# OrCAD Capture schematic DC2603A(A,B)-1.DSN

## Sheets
1 PAGE2: size Custom; title: DC/DC    MODULE REGULATOR; rev: 1; company: TM
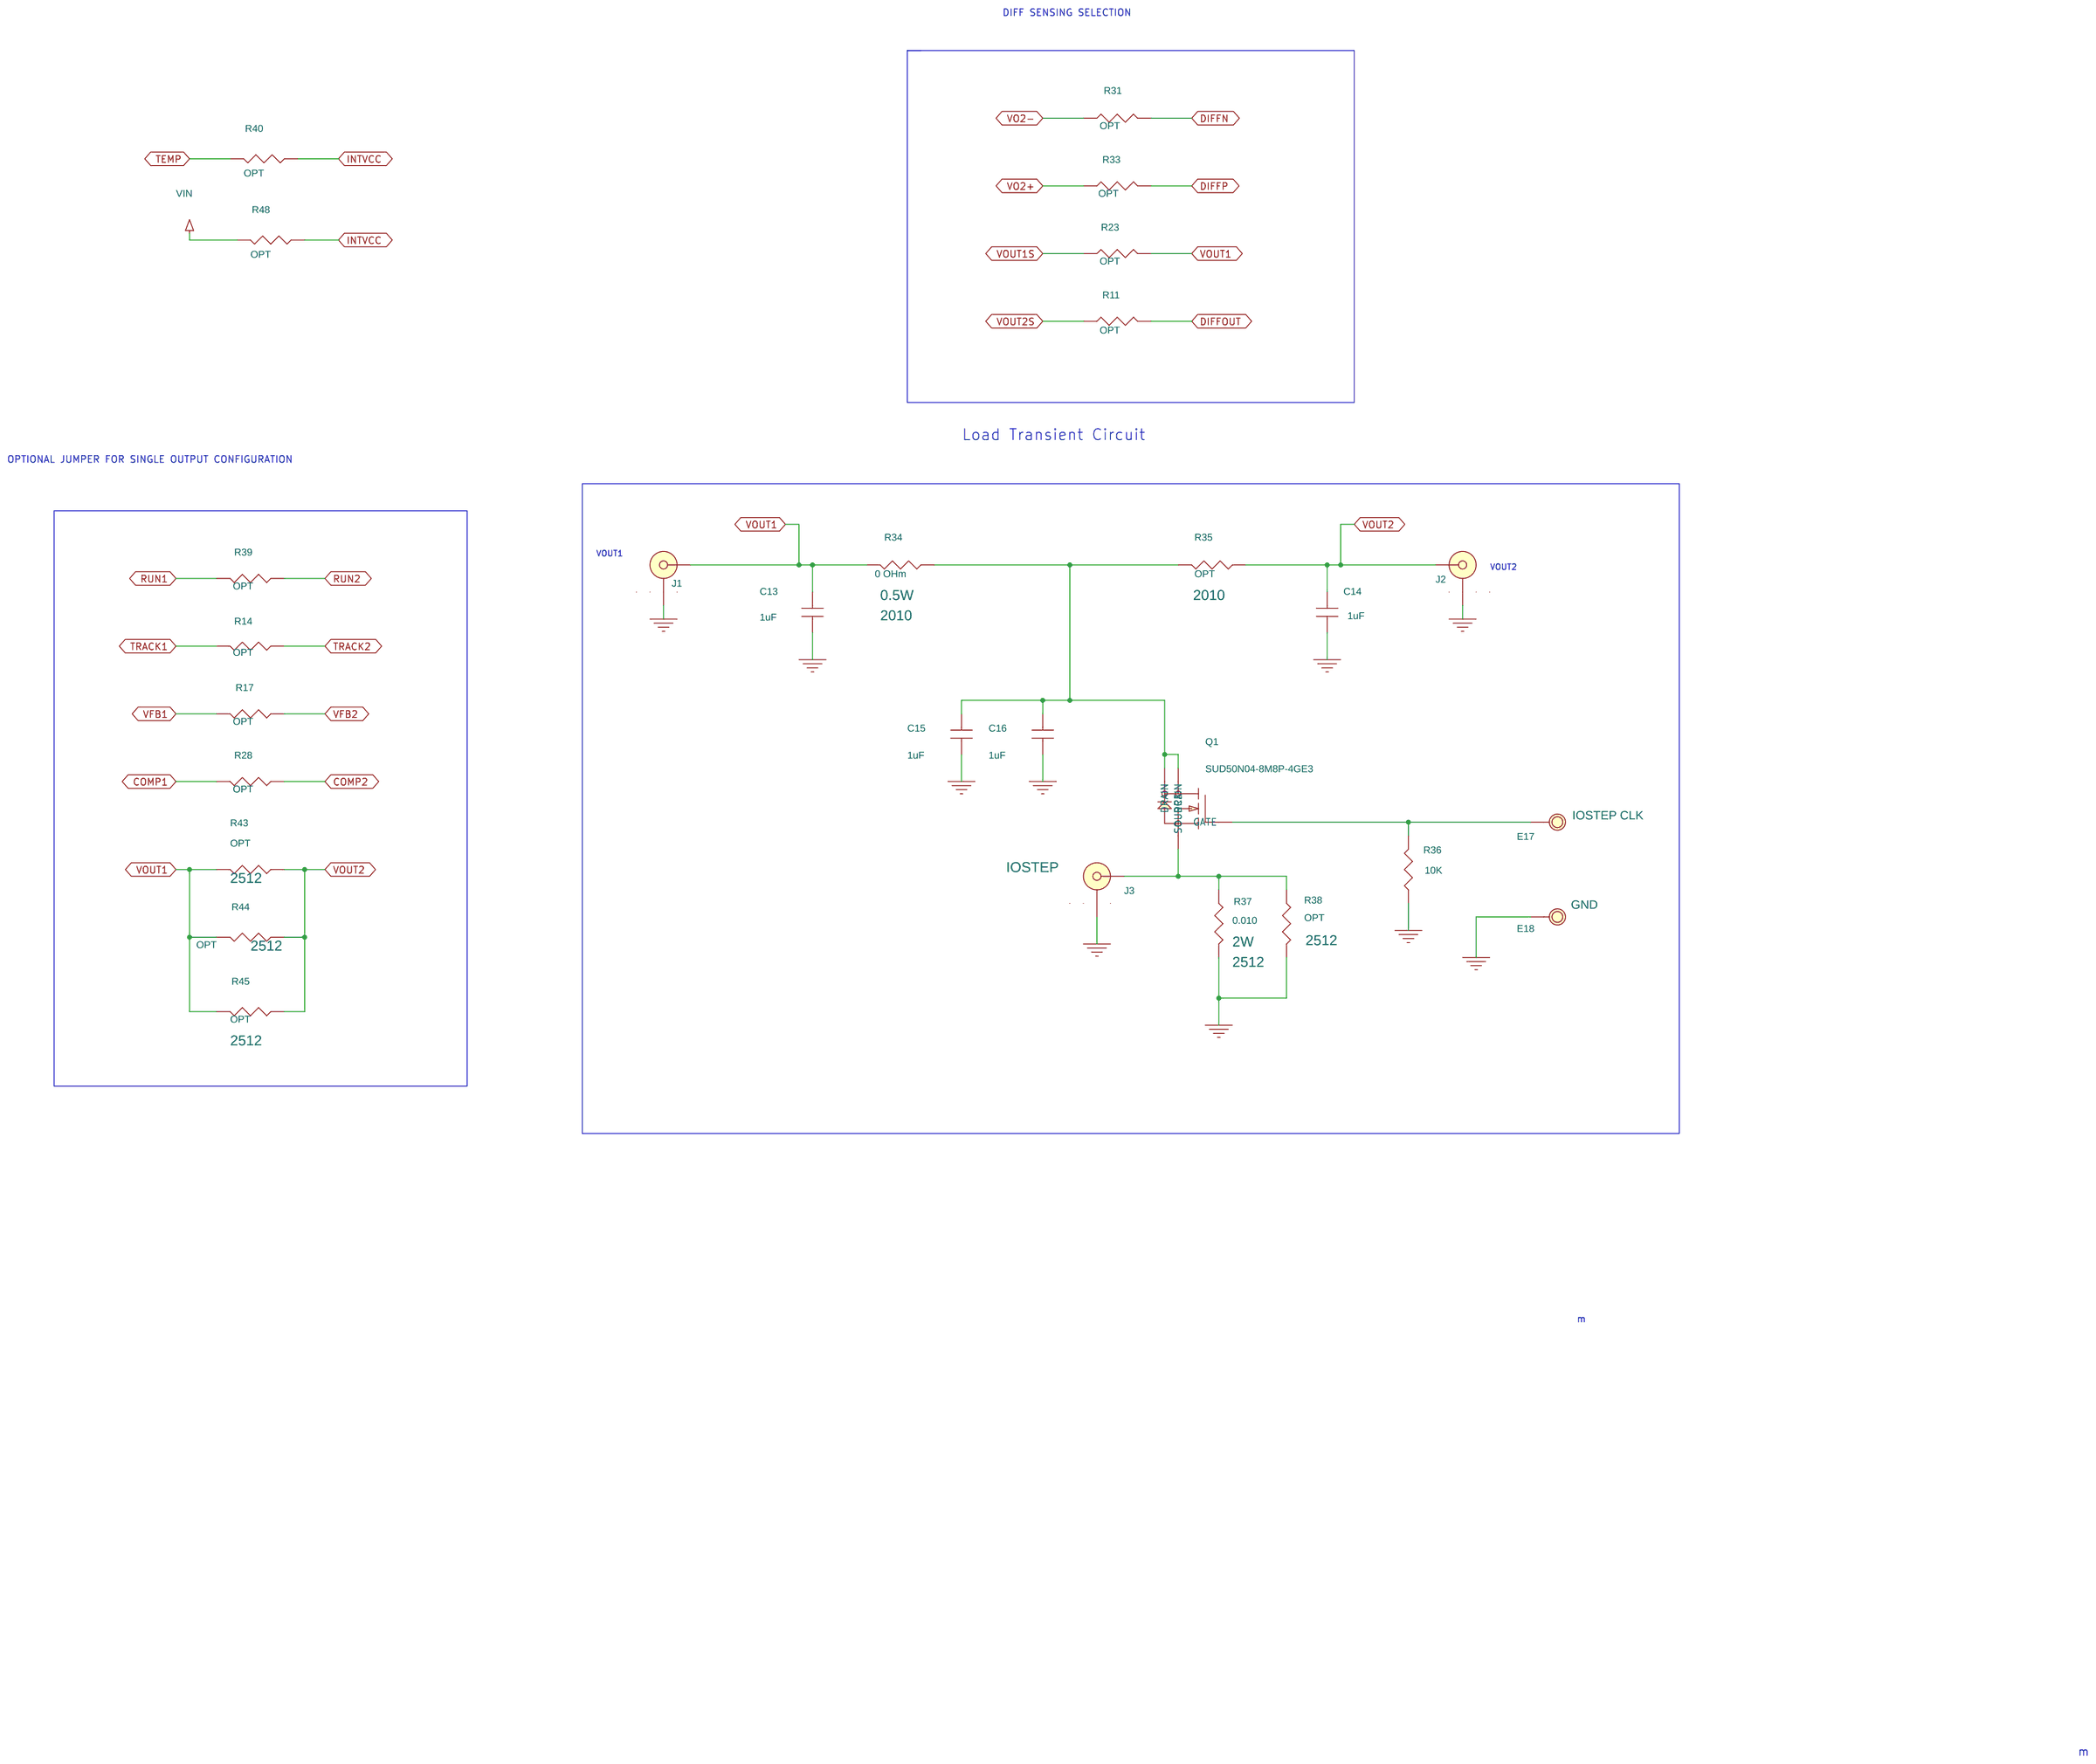
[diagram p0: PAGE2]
2 LTM4650: size Custom
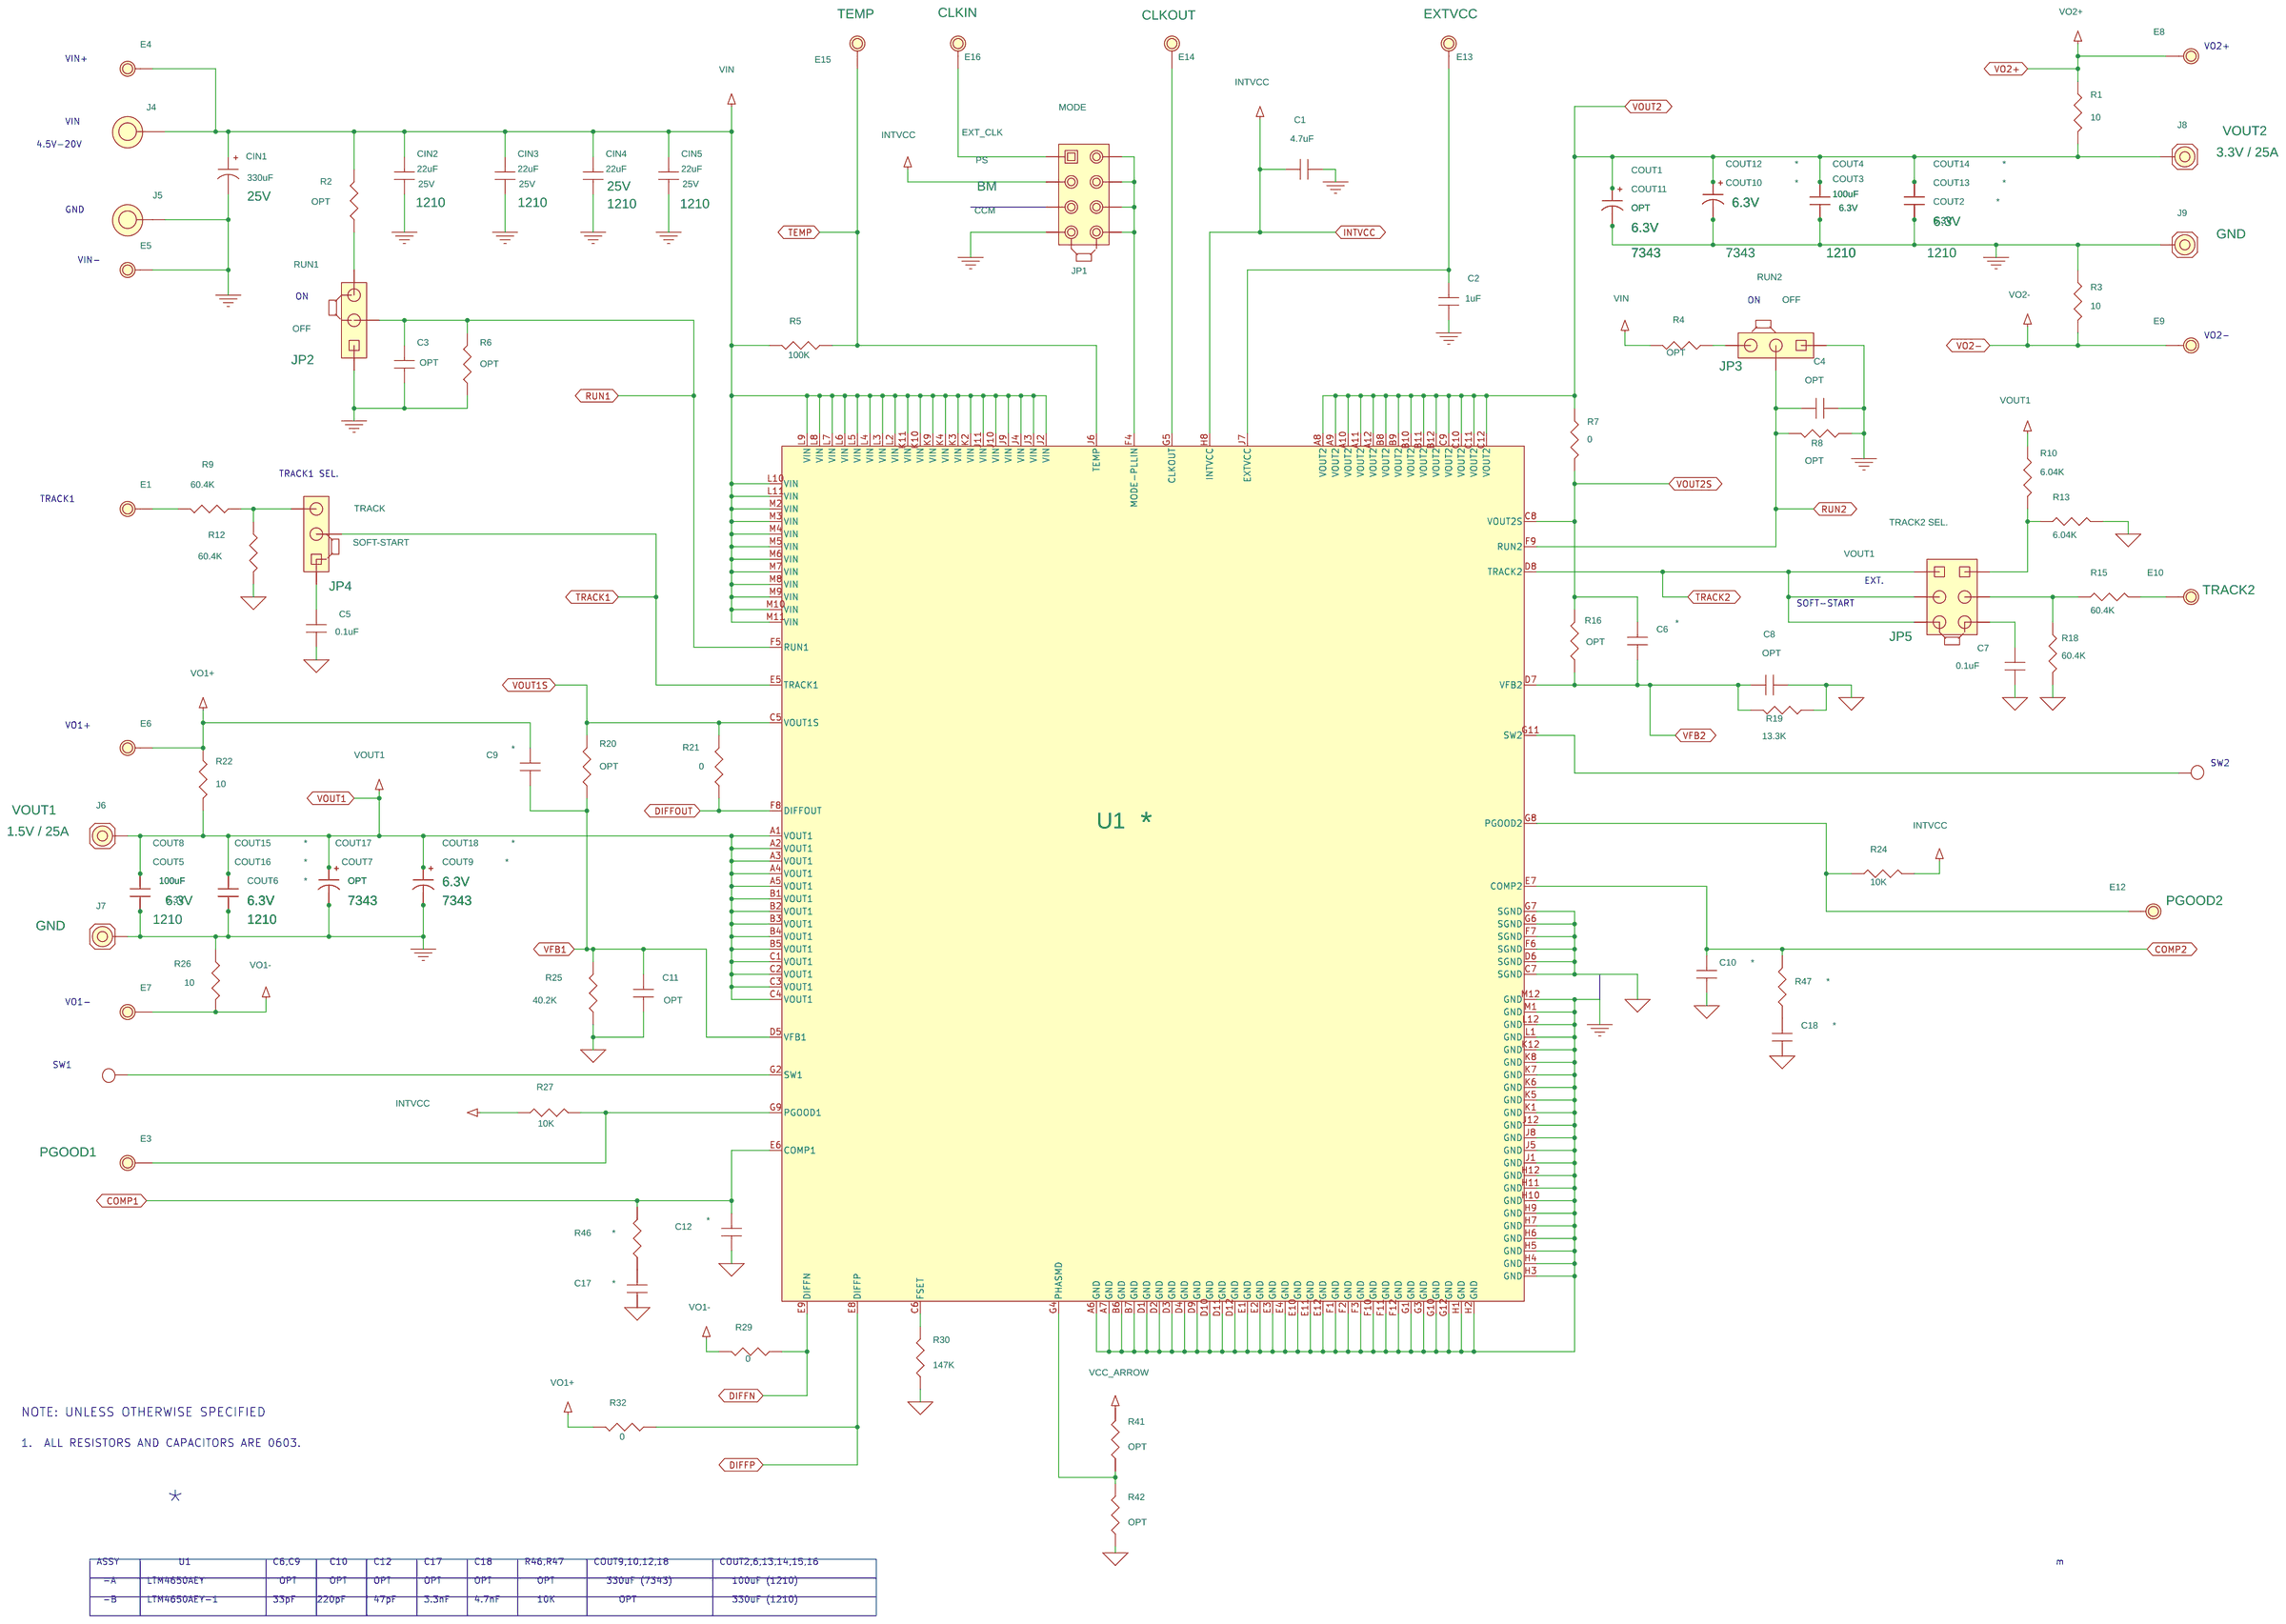
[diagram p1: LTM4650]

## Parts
sheet LTM4650
C1  4.7uF  [0805]
C2  1uF  [0805]
C3  OPT  [0603]
C4  OPT  [0603]
C5  0.1uF  [0603]
C6  *  [0603]
C7  0.1uF  [0603]
C8  OPT  [0603]
C9  *  [0603]
C10  *  [0603]
C11  OPT  [0603]
C12  *  [0603]
C17  *  [0603]
C18  *  [0603]
CIN1  330uF  [C-10X12.5]
CIN2  22uF  [1210]
CIN3  22uF  [1210]
CIN4  22uF  [1210]
CIN5  22uF  [1210]
COUT1  OPT  [7343]
COUT2  *  [1210]
COUT3  100uF  [1210]
COUT4  100uF  [1210]
COUT5  100uF  [1210]
COUT6  *  [1210]
COUT7  OPT  [7343]
COUT8  100uF  [1210]
COUT9  *  [7343]
COUT10  *  [7343]
COUT11  OPT  [7343]
COUT12  *  [7343]
COUT13  *  [1210]
COUT14  *  [1210]
COUT15  *  [1210]
COUT16  *  [1210]
COUT17  OPT  [7343]
COUT18  *  [7343]
E1  Testpoint  [MM/2501]
E3  PGOOD1  [MM/2501]
E4  Testpoint  [MM/2501]
E5  Testpoint  [MM/2501]
E6  Testpoint  [MM/2501]
E7  Testpoint  [MM/2501]
E8  Testpoint  [MM/2501]
E9  Testpoint  [MM/2501]
E10  TRACK2  [MM/2501]
E12  PGOOD2  [MM/2501]
E13  EXTVCC  [MM/2501]
E14  CLKOUT  [MM/2501]
E15  TEMP  [MM/2501]
E16  CLKIN  [MM/2501]
J4  KEY-575--4  [KEY-575-4]
J5  KEY-575--4  [KEY-575-4]
J6  Testpin  [con\lug\10]
J7  Testpin  [con\lug\10]
J8  Testpin  [con\lug\10]
J9  Testpin  [con\lug\10]
JP1  Dbl. Row 2 x 3 2mm Ctrs.  [HD2X4-079]
JP2  3 Pins 2mm Ctrs.  [commcon2802s03g2]
JP3  3 Pins 2mm Ctrs.  [commcon2802s03g2]
JP4  3 Pins 2mm Ctrs.  [commcon2802s03g2]
JP5  3 Pins 2mm Ctrs.  [HD2X3-079]
P1  SMD PAD  [SM/TP]
P2  SMD PAD  [SM/TP]
R1  10  [0603]
R2  OPT  [0603]
R3  10  [0603]
R4  OPT  [0603]
R5  100K  [0603]
R6  OPT  [0603]
R7  0  [0603]
R8  OPT  [0603]
R9  60.4K  [0603]
R10  6.04K  [0603]
R12  60.4K  [0603]
R13  6.04K  [0603]
R15  60.4K  [0603]
R16  OPT  [0603]
R18  60.4K  [0603]
R19  13.3K  [0603]
R20  OPT  [0603]
R21  0  [0603]
R22  10  [0603]
R24  10K  [0603]
R25  40.2K  [0603]
R26  10  [0603]
R27  10K  [0603]
R29  0  [0603]
R30  147K  [0603]
R32  0  [0603]
R41  OPT  [0603]
R42  OPT  [0603]
R46  *  [0603]
R47  *  [0603]
U1  *  [LGA-16X16-144]
XJP2  2mm Ctrs.
XJP3  2mm Ctrs.
XJP4  2mm Ctrs.
XJP5  2mm Ctrs.
XJP7  2mm Ctrs.
sheet PAGE2
C13  1uF  [0603]
C14  1uF  [0603]
C15  1uF  [0603]
C16  1uF  [0603]
E17  IOSTEP CLK  [MM/2501]
E18  GND  [MM/2501]
J1  CON-SMA-EDGE  [BNC5]
J2  CON-SMA-EDGE  [BNC5]
J3  IOSTEP  [BNC5]
Q1  SUD50N04-8M8P-4GE3  [TO252]
R11  OPT  [0603]
R14  OPT  [0603]
R17  OPT  [0603]
R23  OPT  [0603]
R28  OPT  [0603]
R31  OPT  [0603]
R33  OPT  [0603]
R34  0 OHm  [2010]
R35  OPT  [2010]
R36  10K  [0603]
R37  0.010  [2512]
R38  OPT  [2512]
R39  OPT  [0603]
R40  OPT  [0603]
R43  OPT  [2512]
R44  OPT  [2512]
R45  OPT  [2512]
R48  OPT  [0603]

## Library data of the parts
C1-C5 C7 CIN2-CIN5 = CAP1206: 1ST PART FIELD: 25V; 2ND PART FIELD: 0805-1206
C6 C8-C12 C17 C18 COUT3 COUT4 COUT13 COUT14 = CAP1206: 1ST PART FIELD: 6.3V; 2ND PART FIELD: 0805-1206
CIN1 = CAP-SVPA-E7: 1ST PART FIELD: 25V
COUT1 COUT9-COUT12 COUT18 = CAP-SVPA-E7: 1ST PART FIELD: 6.3V
COUT2 = CAP1206: 1ST PART FIELD: 25V; 2ND PART FIELD: 0805-1206; VOLTAGE: 6.3V
COUT5 = CAP1210: 1ST PART FIELD: 6.3V; 2ND PART FIELD: 1210-3743
COUT6 COUT8 COUT15 COUT16 = CAP1206: 1ST PART FIELD: 6.3V; 2ND PART FIELD: 0805-1206; VOLTAGE: 6.3V
COUT7 COUT17 = CAP-SVPA-E7: 1ST PART FIELD: 2.5V
E1 E3-E10 E12-E18 = MillMax-2501_1
J4 J5 = KEY-575--4_1
J6 = PEM-kfh-032-10_0: STUD; 10th Part Field: 100 AMP; 11th Part Field: 1.5V / 25A; 9th Part Field: VOUT1; Part Number: PEM KFH-032-10
J7 J9 = PEM-kfh-032-10_0: STUD; 10th Part Field: 100 AMP; 11th Part Field: 1V / 25A; 9th Part Field: GND; Part Number: PEM KFH-032-10
J8 = PEM-kfh-032-10_0: STUD; 10th Part Field: 100 AMP; 11th Part Field: 3.3V / 25A; 9th Part Field: VOUT2; Part Number: PEM KFH-032-10
JP1 = Samtec_TMM-103-02-L-D_0: 10th Part Field: PS; 11th Part Field: CCM; 12th Part Field: MODE; 9th Part Field: EXT_CLK; PIN5: BM
JP2 = Commcon2802s03g2_1: 11th Part Field: OFF; 12th Part Field: RUN1; 9th Part Field: ON
JP3 = Commcon2802s03g2_1: 11th Part Field: OFF; 12th Part Field: RUN2; 9th Part Field: ON
JP4 = Commcon2802s03g2_2: 11th Part Field: SOFT-START; 12th Part Field: TRACK; 9th Part Field: ON
JP5 = Commcon2802s03g2_4: 11th Part Field: VOUT1; 12th Part Field: TRACK2 SEL.; 9th Part Field: ON
P1 P2 = PAD_2: Component: tp; Label: <Label>; Vendor: Digikey; Vendor P/N: 1593-2K-ND
R1-R33 R36 R39-R48 = AAC-0603
U1 = LTM4620_15
XJP2-XJP5 XJP7 = CommconCCIJ2MM-138G
C13-C16 = CAP0402
J1-J3 = CON-SMA-EDGE_0
Q1 = IRF540_0
R34 R35 = AAC-0603: 1ST PART FIELD: 0.5W
R37 R38 = AAC-0603: 1ST PART FIELD: 2W

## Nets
GND: C1.2 C2.2 C3.2 C4.2 C13.2 C14.2 C15.2 C16.2 CIN1.2 CIN2.2 CIN3.2 CIN4.2 CIN5.2 COUT1.2 COUT2.2 COUT3.2 COUT4.2 COUT5.2 COUT6.2 COUT7.2 COUT8.2 COUT9.2 COUT10.2 COUT11.2 COUT12.2 COUT13.2 COUT14.2 COUT15.2 COUT16.2 COUT17.2 COUT18.2 E5.1 E18.1 J1.2(GND) J1.3 J1.4(GND) J1.5(GND) J2.2(GND) J2.3 J2.4(GND) J2.5(GND) J3.2(GND) J3.3 J3.4(GND) J3.5(GND) J5.1 J7.1 J9.1 JP1.7 JP2.1 JP3.1 R3.1 R6.1 R8.1 R26.1 R36.1 R37.2 R38.2 U1.A6(GND) U1.A7(GND) U1.B6(GND) U1.B7(GND) U1.D1(GND) U1.D2(GND) U1.D3(GND) U1.D4(GND) U1.D9(GND) U1.D10(GND) U1.D11(GND) U1.D12(GND) U1.E1(GND) U1.E2(GND) U1.E3(GND) U1.E4(GND) U1.E10(GND) U1.E11(GND) U1.E12(GND) U1.F1(GND) U1.F2(GND) U1.F3(GND) U1.F10(GND) U1.F11(GND) U1.F12(GND) U1.G1(GND) U1.G3(GND) U1.G10(GND) U1.G12(GND) U1.H1(GND) U1.H2(GND) U1.H3(GND) U1.H4(GND) U1.H5(GND) U1.H6(GND) U1.H7(GND) U1.H9(GND) U1.H10(GND) U1.H11(GND) U1.H12(GND) U1.J1(GND) U1.J5(GND) U1.J8(GND) U1.J12(GND) U1.K1(GND) U1.K5(GND) U1.K6(GND) U1.K7(GND) U1.K8(GND) U1.K12(GND) U1.L1(GND) U1.L12(GND) U1.M1(GND) U1.M12(GND)
GND_SIGNAL: C5.2 C7.2 C8.2 C10.2 C11.2 C12.2 C17.2 C18.2 R12.2 R13.2 R18.2 R19.1 R25.1 R30.1 R42.1 U1.C7(SGND) U1.D6(SGND) U1.F6(SGND) U1.F7(SGND) U1.G6(SGND) U1.G7(SGND)
VIN: CIN1.1 CIN2.1 CIN3.1 CIN4.1 CIN5.1 E4.1 J4.1 R2.2 R4.2 R5.2 R48.2 U1.J2(VIN) U1.J3(VIN) U1.J4(VIN) U1.J9(VIN) U1.J10(VIN) U1.J11(VIN) U1.K2(VIN) U1.K3(VIN) U1.K4(VIN) U1.K9(VIN) U1.K10(VIN) U1.K11(VIN) U1.L2(VIN) U1.L3(VIN) U1.L4(VIN) U1.L5(VIN) U1.L6(VIN) U1.L7(VIN) U1.L8(VIN) U1.L9(VIN) U1.L10(VIN) U1.L11(VIN) U1.M2(VIN) U1.M3(VIN) U1.M4(VIN) U1.M5(VIN) U1.M6(VIN) U1.M7(VIN) U1.M8(VIN) U1.M9(VIN) U1.M10(VIN) U1.M11(VIN)
COMP1: C12.1 R28.2 R46.2 U1.E6(COMP1)
COMP2: C10.1 R28.1 R47.2 U1.E7(COMP2)
DIFFN: R29.1 R31.2 U1.E9(DIFFN)
DIFFOUT: R11.2 R21.1 U1.F8(DIFFOUT)
DIFFP: R32.1 R33.2 U1.E8(DIFFP)
INTVCC: C1.1 JP1.3 R24.2 R27.1 R40.1 R41.2 R48.1 U1.H8(INTVCC)
RUN1: C3.1 JP2.2 R6.2 R39.2 U1.F5(RUN1)
RUN2: C4.1 JP3.2 R8.2 R39.1 U1.F9(RUN2)
TEMP: E15.1 R5.1 R40.2 U1.J6(TEMP)
TRACK1: JP4.2 R14.2 U1.E5(TRACK1)
TRACK2: JP5.1 JP5.3 JP5.5 R14.1 U1.D8(TRACK2)
VFB1: C9.2 C11.1 R17.2 R20.1 R25.2 U1.D5(VFB1)
VFB2: C6.2 C8.1 R16.1 R17.1 R19.2 U1.D7(VFB2)
VO1+: C9.1 E6.1 R22.1 R32.2
VO1-: E7.1 R26.2 R29.2
VO2+: E8.1 R1.1 R33.1
VO2-: E9.1 R3.2 R31.1
VOUT1: C13.1 COUT5.1 COUT6.1 COUT7.1 COUT8.1 COUT9.1 COUT15.1 COUT16.1 COUT17.1 COUT18.1 J1.1 J6.1 R10.1 R22.2 R23.2 R34.2 R43.2 R44.2 R45.2 U1.A1(VOUT1) U1.A2(VOUT1) U1.A3(VOUT1) U1.A4(VOUT1) U1.A5(VOUT1) U1.B1(VOUT1) U1.B2(VOUT1) U1.B3(VOUT1) U1.B4(VOUT1) U1.B5(VOUT1) U1.C1(VOUT1) U1.C2(VOUT1) U1.C3(VOUT1) U1.C4(VOUT1)
VOUT1S: R20.2 R21.2 R23.1 U1.C5(VOUT1S)
VOUT2: C14.1 COUT1.1 COUT2.1 COUT3.1 COUT4.1 COUT10.1 COUT11.1 COUT12.1 COUT13.1 COUT14.1 J2.1 J8.1 R1.2 R7.1 R35.1 R43.1 R44.1 R45.1 U1.A8(VOUT2) U1.A9(VOUT2) U1.A10(VOUT2) U1.A11(VOUT2) U1.A12(VOUT2) U1.B8(VOUT2) U1.B9(VOUT2) U1.B10(VOUT2) U1.B11(VOUT2) U1.B12(VOUT2) U1.C9(VOUT2) U1.C10(VOUT2) U1.C11(VOUT2) U1.C12(VOUT2)
VOUT2S: C6.1 R7.2 R11.1 R16.2 U1.C8(VOUT2S)
N295820: JP1.2 JP1.4 JP1.6 JP1.8 U1.F4(MODE-PLLIN)
N296492: E14.1 U1.G5(CLKOUT)
N298433: C2.1 E13.1 U1.J7(EXTVCC)
N314575: JP3.3 R4.1
N341598: JP2.3 R2.1
N343284: JP4.3 R9.1 R12.1
N343594: E1.1 R9.2
N356449: P1.1(TP) U1.G2(SW1)
N356544: E3.1 R27.2 U1.G9(PGOOD1)
N372473: R41.1 R42.2 U1.G4(PHASMD)
N375571: JP5.2 R10.2 R13.1
N375697: JP5.4 R15.1 R18.1
N375732: C7.1 JP5.6
N409018: R30.2 U1.C6(FSET)
N412961: P2.1(TP) U1.G11(SW2)
N413641: E12.1 R24.1 U1.G8(PGOOD2)
N421680: C5.1 JP4.1
N484927: E10.1 R15.2
N1254513: C15.1 C16.1 Q1.2(DRAIN) Q1.4(DRAIN) R34.1 R35.2
N1255019: E17.1 Q1.1(GATE) R36.2
N1255527: J3.1 Q1.3(SOURCE) R37.1 R38.1
N16626750: E16.1 JP1.1
N17208457: C17.1 R46.1
N17217276: C18.1 R47.1

Not connected (* = marked no-connect by the designer): JP1 5

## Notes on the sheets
sheet 1
- DIFF SENSING SELECTION
- Load Transient Circuit
- OPTIONAL JUMPER FOR SINGLE OUTPUT CONFIGURATION
- VOUT1
- VOUT2
- m
- m
sheet 2
- VO2+
- VIN+
- VIN
- 4.5V-20V
- GND
- VIN-
- ON
- ON
- VO2-
- TRACK1 SEL.
- TRACK1
- EXT.
- SOFT-START
- VO1+
- SW2
- VO1-
- SW1
- NOTE: UNLESS OTHERWISE SPECIFIED
- 1.  ALL RESISTORS AND CAPACITORS ARE 0603.
- *
- ASSY
- U1
- C6,C9
- C10
- C12
- C17
- C18
- R46,R47
- COUT9,10,12,18
- COUT2,6,13,14,15,16
- m
- -A
- LTM4650AEY
- OPT
- OPT
- OPT
- OPT
- OPT
- OPT
- 330uF (7343)
- 100uF (1210)
- -B
- LTM4650AEY-1
- 33pF
- 220pF
- 47pF
- 3.3nF
- 4.7nF
- 10K
- OPT
- 330uF (1210)
